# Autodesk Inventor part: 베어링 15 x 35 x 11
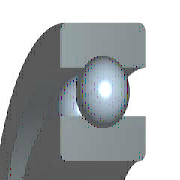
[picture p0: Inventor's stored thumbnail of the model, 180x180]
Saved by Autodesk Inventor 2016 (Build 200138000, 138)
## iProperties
Created: 2012-02
Part Number: 베어링 15 x 35 x 11
Material: 강철, 연강
Description: 깊은 그루브 볼 베어링
Document SubType Name: Modeling
Standard: KS B 2023
Designer: mduedu
Standards Organization: KS
Language: ko-KR
Size Designation: 6202 - 15 x 35 x 11
Categories: <MemberInstance><Categories><Category DisplayName="샤프트 부품" InternalName="7f7aeb1f-a693-4053-b835-cee3144e0d98" Mnemonic="SHFT"><Category DisplayName="베어링" Inter
Density: 1 g/cm^3
Appearance: 노란색
IsCustomPart: 1
Author: mduedu
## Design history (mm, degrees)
sketch "스케치" dims "d0" = 5.2 (= -0.26 x WD + 0.26 x BD)
  geometry: L1 (2.9, 12.5)-(8.1, 12.5); L2 (5.5, 12.5)-(5.5, 9.9); L3 (5.5, 12.5)-(5.5, 15.1); L4 (3.568, 10.76)-(0, 10.76); L5 (0, 7.5)-(11, 7.5); L6 (3.568, 14.24)-(0, 14.24); L7 (0, 17.5)-(11, 17.5); L8 (11, 7.5)-(11, 10.76); L9 (7.432, 10.76)-(11, 10.76); L10 (7.432, 14.24)-(11, 14.24); L11 (11, 17.5)-(11, 14.24); L12 (-1.4, 0)-(8.4, 0) reference; L13 (0, -0.3)-(0, 5.3) reference
  constraints: 22 end point, 4 point on line, 2 collinear, 2 perpendicular, 2 symmetric about line, 1 midpoint, 1 parallel, 14 other
  dimensions: "d9" = 15 diameter of L5 L12 (= WD); "d11" = 35 diameter of L7 L12 (= BD); "d12" = 11 distance between parallel lines of L8 L13 (= KB); "d13" = 21.52 diameter of L9 L12 (= 0.326 x BD + 0.674 x WD)
revolve "본체" stored, may be unused: angle "d6" = 90 deg
revolve "볼" stored, may be unused: angle "d7" = 90 deg
pattern_circular "IDS_ARRAYBALL[SIMPL:T]" dims angle "d3" = 360 deg
body "Solid1"
fillet "모깎기1" dims "d1" = 0.6 (= KRS)
other parameters: "WD" = 15 [user parameter; used in 5 equation terms], "BD" = 35 [user parameter; used in 5 equation terms], "KB" = 11 [user parameter; used in 1 equation term], "KRS" = 0.6 [user parameter; used in 1 equation term], "d4" = 0, "d5" = 0, "d8" = 0, "d14" = 0, "d15" = 0, "BBA" = 0 [user parameter], "BC0" = 3750000 [user parameter], "BC" = 7800000 [user parameter], "BR" = 17.5 (= 0.5 x BD) [user parameter], "WR" = 7.5 (= 0.5 x WD) [user parameter]
